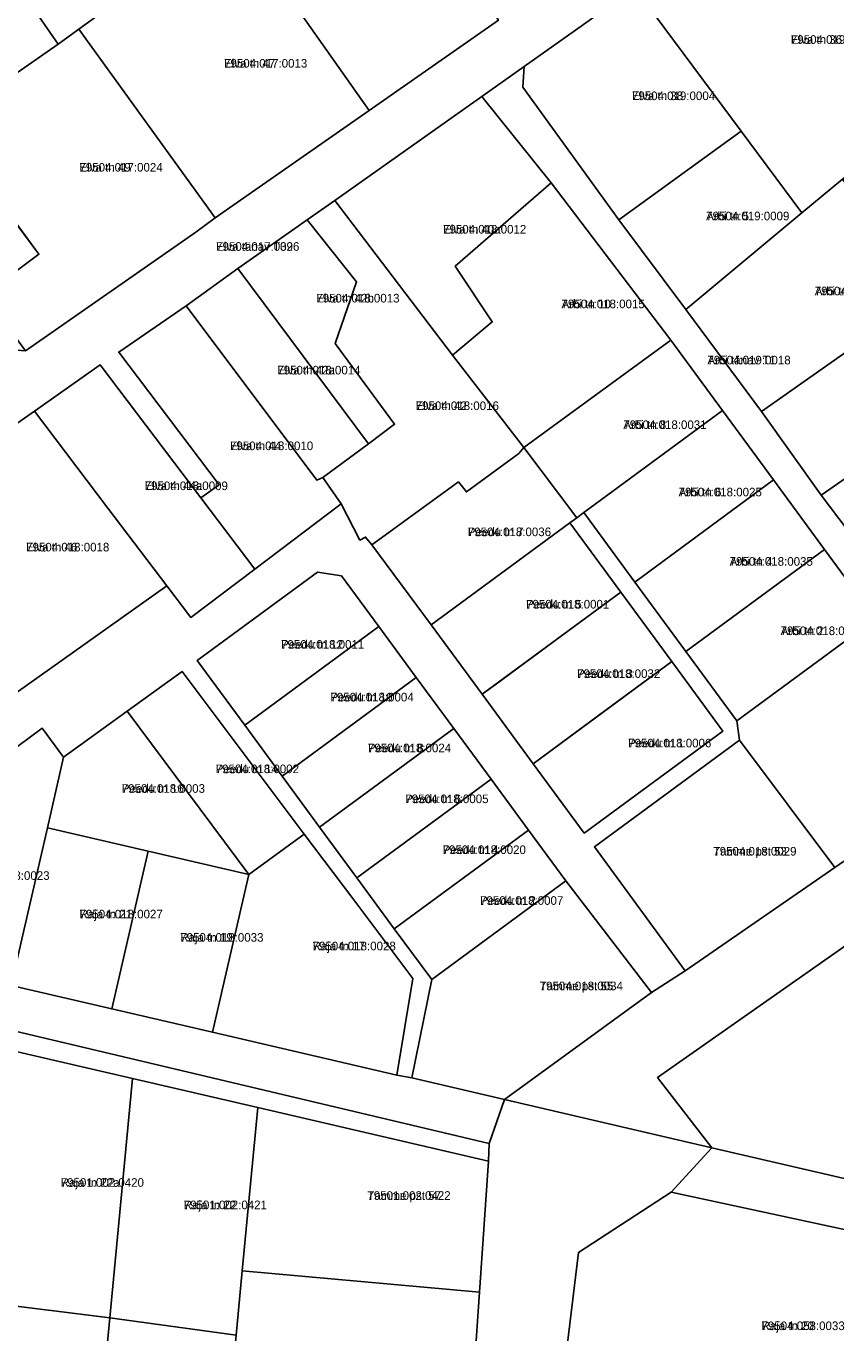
# Model space of a CAD drawing. Extents: x 643847 to 663718, y 6468443 to 6482775.
# Drawn here: x 657785.3 to 657926.4, y 6472032 to 6472259.5 of the extents above; entities that cross this region are included whole.
import ezdxf

# ---------------------------------------------------------------- set-up
doc = ezdxf.new("R2010")
doc.units = 0
for name, color, linetype in [('L_AADRESS', 7, 'Continuous'), ('PIIR', 7, 'Continuous'), ('TUNNUS', 7, 'Continuous')]:
    doc.layers.add(name, color=color, linetype=linetype)

msp = doc.modelspace()

# ---------------------------------------------------------------- linework, layer by layer
at = {"layer": 'PIIR'}
for points in [[(657785.96, 6472294.09), (657805, 6472266.64), (657794.51, 6472258.95), (657790.86, 6472256.37), (657771.65, 6472284.02)], [(657771.65, 6472284.02), (657790.86, 6472256.37), (657776.49, 6472246.35), (657757.34, 6472273.95)], [(657917.78, 6472284.21), (657945.7, 6472247.12), (657927.49, 6472232.86), (657920.45, 6472227), (657909.86, 6472241.24), (657891.33, 6472266.16)], [(657818.24, 6472226.11), (657794.51, 6472258.95), (657805, 6472266.64), (657818.24, 6472276.32), (657821.37, 6472278.45), (657830.98, 6472264.78), (657845.05, 6472244.8)], [(657845.05, 6472244.8), (657830.98, 6472264.78), (657842.58, 6472272.81), (657857.49, 6472275.35), (657867.58, 6472260.54)], [(657909.86, 6472241.24), (657888.57, 6472225.79), (657871.8, 6472248.9), (657872.07, 6472252.45), (657891.33, 6472266.16)], [(657770.93, 6472242.4), (657776.49, 6472246.35), (657790.86, 6472256.37), (657794.51, 6472258.95), (657818.24, 6472226.11), (657814.84, 6472223.63), (657785.21, 6472202.94), (657778.01, 6472212.74), (657787.54, 6472219.77), (657782.2, 6472227.02)], [(657864.71, 6472247.24), (657872.07, 6472252.45), (657871.8, 6472248.9), (657888.57, 6472225.79), (657900.2, 6472210.14), (657913.39, 6472192.41), (657923.78, 6472177.85), (657934.47, 6472163.73), (657943.24, 6472152.43), (657938.51, 6472149.17), (657933.27, 6472156.3), (657924.38, 6472168.39), (657915.49, 6472180.47), (657906.61, 6472192.55), (657897.6, 6472204.8), (657876.79, 6472232.2)], [(657864.71, 6472247.24), (657876.79, 6472232.2), (657860.05, 6472217.71), (657866.49, 6472207.99), (657859.55, 6472202.18), (657839.07, 6472229.12)], [(657749.63, 6472227.26), (657770.93, 6472242.4), (657787.54, 6472219.77), (657778.01, 6472212.74), (657785.21, 6472202.94), (657766.52, 6472204.39)], [(657888.57, 6472225.79), (657909.86, 6472241.24), (657920.45, 6472227), (657900.2, 6472210.14)], [(657897.6, 6472204.8), (657872.03, 6472186.14), (657859.55, 6472202.18), (657866.49, 6472207.99), (657860.05, 6472217.71), (657876.79, 6472232.2)], [(657900.2, 6472210.14), (657920.45, 6472227), (657927.49, 6472232.86), (657942.77, 6472213.06), (657940.79, 6472211.67), (657922.38, 6472198.74), (657913.39, 6472192.41)], [(657839.07, 6472229.12), (657859.55, 6472202.18), (657872.03, 6472186.14), (657871.14, 6472185.09), (657862, 6472178.38), (657860.61, 6472180.14), (657845.54, 6472169.17), (657844.45, 6472170.54), (657843.44, 6472170.01), (657840.19, 6472176.3), (657836.99, 6472180.9), (657844.93, 6472186.79), (657849.5, 6472190.17), (657839.14, 6472204.24), (657842.84, 6472215), (657834.28, 6472225.76)], [(657834.28, 6472225.76), (657842.84, 6472215), (657839.14, 6472204.24), (657849.5, 6472190.17), (657844.93, 6472186.79), (657822.2, 6472217.3)], [(657822.2, 6472217.3), (657844.93, 6472186.79), (657836.99, 6472180.9), (657835.92, 6472180.44), (657813.19, 6472210.82)], [(657913.39, 6472192.41), (657922.38, 6472198.74), (657940.79, 6472211.67), (657951.77, 6472197.17), (657939.72, 6472188.85), (657923.78, 6472177.85)], [(657835.92, 6472180.44), (657836.99, 6472180.9), (657840.19, 6472176.3), (657825.16, 6472164.96), (657815.74, 6472177.39), (657818.95, 6472179.63), (657801.43, 6472202.74), (657813.19, 6472210.82)], [(657906.61, 6472192.55), (657882.44, 6472174.79), (657881.23, 6472173.9), (657872.03, 6472186.14), (657897.6, 6472204.8)], [(657798.22, 6472200.5), (657815.74, 6472177.39), (657825.16, 6472164.96), (657813.99, 6472156.53), (657809.82, 6472162.03), (657799.55, 6472175.57), (657786.75, 6472192.47)], [(657786.75, 6472192.47), (657799.55, 6472175.57), (657809.82, 6472162.03), (657783.57, 6472143.38), (657773.54, 6472156.98), (657760.77, 6472174.29)], [(657915.49, 6472180.47), (657891.33, 6472162.7), (657882.44, 6472174.79), (657906.61, 6472192.55)], [(657943.24, 6472152.43), (657934.47, 6472163.73), (657923.78, 6472177.85), (657939.72, 6472188.85), (657958.71, 6472163.1)], [(657855.86, 6472155.24), (657845.54, 6472169.17), (657860.61, 6472180.14), (657862, 6472178.38), (657871.14, 6472185.09), (657872.03, 6472186.14), (657881.23, 6472173.9), (657880.02, 6472173.01)], [(657915.49, 6472180.47), (657924.38, 6472168.39), (657900.21, 6472150.62), (657891.33, 6472162.7)], [(657855.86, 6472155.24), (657880.02, 6472173.01), (657888.91, 6472160.92), (657864.74, 6472143.16)], [(657933.27, 6472156.3), (657909.1, 6472138.53), (657900.21, 6472150.62), (657924.38, 6472168.39)], [(657846.75, 6472154.93), (657823.39, 6472137.75), (657815.09, 6472149.03), (657836.04, 6472164.43), (657840.24, 6472163.79)], [(657873.63, 6472131.07), (657864.74, 6472143.16), (657867.01, 6472144.82), (657877.47, 6472152.51), (657888.91, 6472160.92), (657897.8, 6472148.84), (657886.35, 6472140.42), (657878.59, 6472134.72)], [(657926.17, 6472112.98), (657909.57, 6472135.15), (657909.1, 6472138.53), (657933.27, 6472156.3), (657952.01, 6472130.83)], [(657853.26, 6472146.08), (657829.9, 6472128.89), (657823.39, 6472137.75), (657846.75, 6472154.93)], [(657882.52, 6472118.99), (657873.63, 6472131.07), (657897.8, 6472148.84), (657906.69, 6472136.75)], [(657812.48, 6472147.15), (657833.76, 6472118.81), (657824.08, 6472111.78), (657802.93, 6472140.22)], [(657859.78, 6472137.22), (657836.41, 6472120.04), (657829.9, 6472128.89), (657853.26, 6472146.08)], [(657802.93, 6472140.22), (657824.08, 6472111.78), (657806.54, 6472115.84), (657789, 6472119.9), (657791.84, 6472132.18)], [(657762.73, 6472118.44), (657788.1, 6472137.24), (657791.84, 6472132.18), (657789, 6472119.9), (657782.68, 6472092.42), (657757.94, 6472098.16)], [(657866.29, 6472128.36), (657842.92, 6472111.18), (657836.41, 6472120.04), (657859.78, 6472137.22)], [(657900.12, 6472095), (657884.3, 6472116.58), (657909.57, 6472135.15), (657926.17, 6472112.98)], [(657872.8, 6472119.5), (657849.44, 6472102.32), (657842.92, 6472111.18), (657866.29, 6472128.36)], [(657789, 6472119.9), (657806.54, 6472115.84), (657800.22, 6472088.36), (657782.68, 6472092.42)], [(657817.76, 6472084.3), (657824.08, 6472111.78), (657833.76, 6472118.81), (657842.19, 6472107.57), (657852.64, 6472093.66), (657849.9, 6472076.85)], [(657855.95, 6472093.47), (657849.44, 6472102.32), (657872.8, 6472119.5), (657879.31, 6472110.65)], [(657800.22, 6472088.36), (657806.54, 6472115.84), (657824.08, 6472111.78), (657817.76, 6472084.3)], [(657679.89, 6472105), (657667.58, 6472108), (657667.96, 6472111.85), (657865.98, 6472064.91), (657865.84, 6472061.88), (657825.65, 6472071.2), (657803.82, 6472076.24), (657783.06, 6472081.07), (657759.6, 6472086.51), (657737.69, 6472091.6), (657717.47, 6472096.29)], [(657894.25, 6472091.21), (657868.62, 6472072.59), (657852.52, 6472076.39), (657855.95, 6472093.47), (657879.31, 6472110.65)], [(657939.59, 6472107.45), (657958.35, 6472082.91), (657951.15, 6472053.43), (657904.76, 6472064.19), (657895.26, 6472076.4)], [(657778.84, 6472037.2), (657783.06, 6472081.07), (657803.82, 6472076.24), (657799.87, 6472034.55)], [(657799.87, 6472034.55), (657803.82, 6472076.24), (657825.65, 6472071.2), (657822.94, 6472042.73), (657821.89, 6472031.58)], [(657822.94, 6472042.73), (657825.65, 6472071.2), (657865.84, 6472061.88), (657864.27, 6472039.03)], [(657949.65, 6472045.25), (657942.24, 6472010.71), (657942, 6472008.44), (657934.77, 6472010.33), (657907.04, 6472015.95), (657883.03, 6472020.81), (657878.51, 6472021.1), (657881.55, 6472045.97), (657897.69, 6472056.43)], [(657821.89, 6472031.58), (657822.94, 6472042.73), (657864.27, 6472039.03), (657862.56, 6472013.73), (657820.54, 6472017.46)], [(657774.87, 6471995.33), (657778.84, 6472037.2), (657799.87, 6472034.55), (657795.9, 6471992.91)], [(657795.9, 6471992.91), (657799.87, 6472034.55), (657821.89, 6472031.58), (657820.54, 6472017.46), (657818.04, 6471990.35)]]:
    msp.add_lwpolyline(points, close=True, dxfattribs=at)
for points in [[(657891.33, 6472266.16), (657872.07, 6472252.45), (657864.71, 6472247.24), (657839.07, 6472229.12), (657834.28, 6472225.76), (657822.2, 6472217.3), (657813.19, 6472210.82), (657801.43, 6472202.74), (657818.95, 6472179.63), (657815.74, 6472177.39), (657798.22, 6472200.5), (657786.75, 6472192.47), (657760.77, 6472174.29)], [(657785.21, 6472202.94), (657814.84, 6472223.63), (657818.24, 6472226.11), (657845.05, 6472244.8), (657867.58, 6472260.54)], [(657783.57, 6472143.38), (657809.82, 6472162.03), (657813.99, 6472156.53), (657825.16, 6472164.96), (657840.19, 6472176.3), (657843.44, 6472170.01), (657844.45, 6472170.54), (657845.54, 6472169.17), (657855.86, 6472155.24), (657864.74, 6472143.16), (657873.63, 6472131.07), (657882.52, 6472118.99), (657906.69, 6472136.75), (657897.8, 6472148.84), (657888.91, 6472160.92), (657880.02, 6472173.01), (657881.23, 6472173.9), (657882.44, 6472174.79), (657891.33, 6472162.7), (657900.21, 6472150.62), (657909.1, 6472138.53), (657909.57, 6472135.15), (657884.3, 6472116.58), (657900.12, 6472095), (657894.25, 6472091.21), (657879.31, 6472110.65), (657872.8, 6472119.5), (657866.29, 6472128.36), (657859.78, 6472137.22), (657853.26, 6472146.08), (657846.75, 6472154.93), (657840.24, 6472163.79), (657836.04, 6472164.43), (657815.09, 6472149.03), (657823.39, 6472137.75), (657829.9, 6472128.89), (657836.41, 6472120.04), (657842.92, 6472111.18), (657849.44, 6472102.32), (657855.95, 6472093.47), (657852.52, 6472076.39), (657849.9, 6472076.85), (657852.64, 6472093.66), (657842.19, 6472107.57), (657833.76, 6472118.81), (657812.48, 6472147.15), (657802.93, 6472140.22), (657791.84, 6472132.18), (657788.1, 6472137.24), (657762.73, 6472118.44)], [(657576.88, 6472140.97), (657616.96, 6472131.44), (657642.03, 6472125.36), (657666.36, 6472119.68), (657698.02, 6472112.04), (657723.93, 6472106.04), (657738.97, 6472102.57), (657751.27, 6472099.71), (657757.94, 6472098.16), (657782.68, 6472092.42), (657800.22, 6472088.36), (657817.76, 6472084.3), (657849.9, 6472076.85), (657852.52, 6472076.39), (657868.62, 6472072.59), (657865.98, 6472064.91), (657667.96, 6472111.85), (657667.58, 6472108), (657664.26, 6472108.82), (657618.18, 6472119.75), (657506.45, 6472146.16)], [(657939.59, 6472107.45), (657895.26, 6472076.4), (657904.76, 6472064.19), (657868.62, 6472072.59), (657894.25, 6472091.21), (657900.12, 6472095), (657926.17, 6472112.98), (657952.01, 6472130.83)], [(658005.46, 6472031.63), (657979.87, 6472037.46), (657949.65, 6472045.25), (657897.69, 6472056.43), (657904.76, 6472064.19), (657951.15, 6472053.43), (657963.03, 6472050.68), (657974.72, 6472047.98), (658005.95, 6472040.44), (658038.68, 6472032.51), (658044.22, 6472061.95), (658055.63, 6472070.49), (658066.9, 6472078.8), (658078.38, 6472087.25), (658081.47, 6472083.26), (658074.69, 6472078.27), (658048.78, 6472059.15), (658044.51, 6472036.55), (658043.53, 6472031.34)], [(657862.56, 6472013.73), (657864.27, 6472039.03), (657865.84, 6472061.88), (657865.98, 6472064.91), (657868.62, 6472072.59), (657904.76, 6472064.19), (657897.69, 6472056.43), (657881.55, 6472045.97), (657878.51, 6472021.1)]]:
    msp.add_lwpolyline(points, dxfattribs=at)

# ---------------------------------------------------------------- texts
at = {"layer": 'L_AADRESS'}
for s, p in [('Elva tn 36', (657918.52, 6472256.42)), ('Elva tn 47', (657819.78, 6472252.28)), ('Elva tn 38', (657890.83, 6472246.62)), ('Elva tn 49', (657794.59, 6472234.17)), ('Arbi tn 5', (657903.76, 6472225.69)), ('Elva tn 40a', (657857.93, 6472223.38)), ('Elva tänav T39', (657818.4, 6472220.38)), ('Arbi tn 3', (657922.68, 6472212.63)), ('Elva tn 42b', (657835.85, 6472211.38)), ('Arbi tn 10', (657878.57, 6472210.38)), ('Arbi tänav T1', (657903.98, 6472200.6)), ('Elva tn 42a', (657829.06, 6472198.85)), ('Elva tn 42', (657853.16, 6472192.65)), ('Arbi tn 8', (657889.34, 6472189.35)), ('Elva tn 44', (657820.81, 6472185.67)), ('Elva tn 44a', (657805.95, 6472178.71)), ('Arbi tn 6', (657898.96, 6472177.62)), ('Peedu tn 7', (657862.25, 6472170.69)), ('Elva tn 46', (657785.3, 6472168.03)), ('Arbi tn 4', (657907.85, 6472165.54)), ('Peedu tn 5', (657872.39, 6472158.09)), ('Arbi tn 2', (657916.74, 6472153.46)), ('Peedu tn 12', (657829.71, 6472151.09)), ('Peedu tn 3', (657881.27, 6472146)), ('Peedu tn 10', (657838.32, 6472141.91)), ('Peedu tn 8', (657844.84, 6472133.06)), ('Peedu tn 1', (657890.17, 6472133.91)), ('Peedu tn 14', (657818.34, 6472129.42)), ('Peedu tn 16', (657801.96, 6472126)), ('Peedu tn 6', (657851.35, 6472124.2)), ('Peedu tn 4', (657857.86, 6472115.34)), ('Tamme pst 53', (657905, 6472115.07)), ('Peedu tn 2', (657864.38, 6472106.49)), ('Raja tn 21', (657794.61, 6472104.13)), ('Raja tn 19', (657812.15, 6472100.07)), ('Raja tn 17', (657835.2, 6472098.57)), ('Tamme pst 55', (657874.76, 6472091.62)), ('Raja tn 22a', (657791.33, 6472057.39)), ('Tamme pst 57', (657844.75, 6472055.12)), ('Raja tn 22', (657812.76, 6472053.49)), ('Raja tn 20', (657913.4, 6472032.44))]:
    msp.add_text(s, height=1.5, dxfattribs=at).set_placement(p)
at = {"layer": 'TUNNUS'}
for s, p in [('79504:019:0001', (657918.52, 6472256.42)), ('79504:017:0013', (657819.78, 6472252.28)), ('79504:019:0004', (657890.83, 6472246.62)), ('79504:017:0024', (657794.59, 6472234.17)), ('79504:019:0009', (657903.76, 6472225.69)), ('79504:018:0012', (657857.93, 6472223.38)), ('79504:017:0026', (657818.4, 6472220.38)), ('79504:019:0008', (657922.68, 6472212.63)), ('79504:018:0013', (657835.85, 6472211.38)), ('79504:018:0015', (657878.57, 6472210.38)), ('79504:019:0018', (657903.98, 6472200.6)), ('79504:018:0014', (657829.06, 6472198.85)), ('79504:018:0016', (657853.16, 6472192.65)), ('79504:018:0031', (657889.34, 6472189.35)), ('79504:018:0010', (657820.81, 6472185.67)), ('79504:018:0009', (657805.95, 6472178.71)), ('79504:018:0025', (657898.96, 6472177.62)), ('79504:018:0036', (657862.25, 6472170.69)), ('79504:018:0018', (657785.3, 6472168.03)), ('79504:018:0035', (657907.85, 6472165.54)), ('79504:018:0001', (657872.39, 6472158.09)), ('79504:018:0017', (657916.74, 6472153.46)), ('79504:018:0011', (657829.71, 6472151.09)), ('79504:018:0032', (657881.27, 6472146)), ('79504:018:0004', (657838.32, 6472141.91)), ('79504:018:0024', (657844.84, 6472133.06)), ('79504:018:0006', (657890.17, 6472133.91)), ('79504:018:0002', (657818.34, 6472129.42)), ('79504:018:0003', (657801.96, 6472126)), ('79504:018:0005', (657851.35, 6472124.2)), ('79504:018:0020', (657857.86, 6472115.34)), ('79504:018:0029', (657905, 6472115.07)), ('79504:018:0023', (657774.89, 6472110.84)), ('79504:018:0007', (657864.38, 6472106.49)), ('79504:018:0027', (657794.61, 6472104.13)), ('79504:018:0033', (657812.15, 6472100.07)), ('79504:018:0028', (657835.2, 6472098.57)), ('79504:018:0034', (657874.76, 6472091.62)), ('79501:002:0420', (657791.33, 6472057.39)), ('79501:002:0422', (657844.75, 6472055.12)), ('79501:002:0421', (657812.76, 6472053.49)), ('79504:058:0033', (657913.4, 6472032.44))]:
    msp.add_text(s, height=1.5, dxfattribs=at).set_placement(p)

doc.saveas('drawing.dxf')
